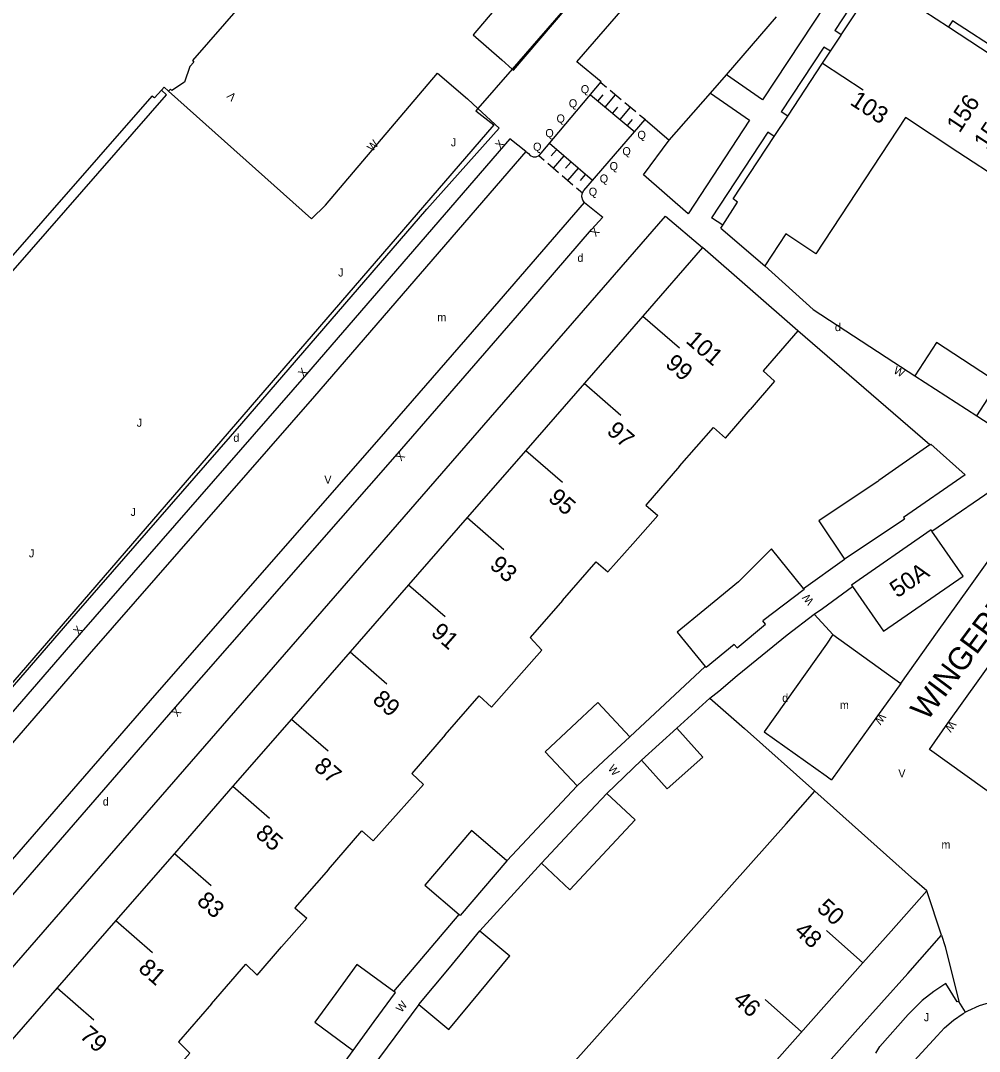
# Model space of a CAD drawing. Extents: x 134999 to 136502, y 457398 to 459002.
# Drawn here: x 135294.2 to 135353.4, y 457659.1 to 457722.8 of the extents above; entities that cross this region are included whole.
import ezdxf

# ---------------------------------------------------------------- set-up
doc = ezdxf.new("R2010")
doc.units = 0
for name, color, linetype in [('RI_DGTB_15', 7, 'Continuous'), ('RI_DGTB_2', 7, 'Continuous'), ('RI_DGTB_29', 7, 'Continuous'), ('RI_DGTB_30', 7, 'Continuous'), ('RI_DGTB_31', 7, 'Continuous'), ('RI_DGTB_35', 7, 'Continuous'), ('RI_DGTB_36', 7, 'Continuous'), ('RI_DGTB_37', 7, 'Continuous'), ('RI_DGTB_4', 7, 'Continuous'), ('RI_DGTB_43', 7, 'Continuous'), ('RI_DGTB_48', 7, 'Continuous'), ('RI_DGTB_5', 7, 'Continuous'), ('RI_DGTB_53', 7, 'Continuous'), ('RI_DGTB_54', 7, 'Continuous'), ('RI_DGTB_55', 7, 'Continuous'), ('RI_DGTB_6', 7, 'Continuous')]:
    doc.layers.add(name, color=color, linetype=linetype)

msp = doc.modelspace()

# ---------------------------------------------------------------- linework, layer by layer
at = {"layer": 'RI_DGTB_15'}
for p, q in [((135343.741, 457720.145), (135346.249, 457718.499)), ((135332.636, 457704.527), (135334.897, 457702.556)), ((135329.018, 457700.378), (135331.279, 457698.407)), ((135325.4, 457696.229), (135327.661, 457694.258)), ((135321.782, 457692.08), (135324.043, 457690.109)), ((135318.164, 457687.931), (135320.425, 457685.96)), ((135314.546, 457683.782), (135316.807, 457681.811)), ((135310.928, 457679.633), (135313.189, 457677.662)), ((135307.31, 457675.484), (135309.571, 457673.513)), ((135303.692, 457671.335), (135305.953, 457669.364)), ((135300.074, 457667.186), (135302.335, 457665.215)), ((135346.225, 457664.577), (135343.982, 457666.569)), ((135296.456, 457663.037), (135298.717, 457661.066)), ((135342.441, 457660.314), (135340.198, 457662.306))]:
    msp.add_line(p, q, dxfattribs=at)
at = {"layer": 'RI_DGTB_2'}
msp.add_line((135337.459, 457709.965), (135340.181, 457707.64), dxfattribs=at)
for points in [[(135344.893, 457721.893), (135347.062, 457725.193), (135347.117, 457725.277), (135347.953, 457724.727)], [(135349.991, 457723.39), (135351.511, 457722.392)], [(135351.511, 457722.392), (135355.473, 457719.793)], [(135344.228, 457720.884), (135344.884, 457721.88), (135344.893, 457721.893)], [(135343.741, 457720.145), (135344.228, 457720.884)], [(135341.587, 457716.875), (135343.741, 457720.145)], [(135348.857, 457716.787), (135343.319, 457708.382), (135341.463, 457709.603), (135340.181, 457707.64)], [(135340.757, 457715.615), (135341.587, 457716.875)], [(135352.102, 457714.66), (135348.857, 457716.787)], [(135337.578, 457710.148), (135338.492, 457711.56), (135338.218, 457711.761), (135340.757, 457715.615)], [(135360.141, 457709.392), (135354.871, 457712.845), (135352.102, 457714.66)], [(135337.459, 457709.965), (135337.578, 457710.148)], [(135350.446, 457691.317), (135345.519, 457687.906), (135345.584, 457687.813)], [(135345.584, 457687.813), (135347.494, 457685.054), (135352.42, 457688.466), (135350.492, 457691.25)], [(135350.492, 457691.25), (135350.446, 457691.317)], [(135341.479, 457673.165), (135343.265, 457675.172)], [(135343.265, 457675.172), (135349.426, 457669.682)], [(135339.304, 457670.719), (135341.479, 457673.165)], [(135335.451, 457666.387), (135339.304, 457670.719)], [(135350.175, 457669.019), (135349.426, 457669.682)], [(135347.976, 457666.538), (135350.175, 457669.019)], [(135331.702, 457662.171), (135335.451, 457666.387)], [(135346.23, 457664.572), (135347.976, 457666.538)], [(135342.377, 457660.238), (135346.23, 457664.572)], [(135327.941, 457657.942), (135331.702, 457662.171)], [(135338.631, 457656.019), (135342.377, 457660.238)]]:
    msp.add_lwpolyline(points, dxfattribs=at)
at = {"layer": 'RI_DGTB_31'}
for p, q in [((135330.037, 457718.963), (135330.382, 457718.675)), ((135329.394, 457718.196), (135332.135, 457715.915)), ((135329.857, 457717.811), (135330.177, 457718.196)), ((135330.314, 457717.431), (135330.953, 457718.2)), ((135330.611, 457718.485), (135331.296, 457717.915)), ((135330.77, 457717.051), (135331.09, 457717.436)), ((135331.227, 457716.671), (135331.867, 457717.44)), ((135331.524, 457717.725), (135332.209, 457717.155)), ((135331.684, 457716.291), (135332.003, 457716.676)), ((135332.437, 457716.965), (135332.79, 457716.672)), ((135329.524, 457712.897), (135326.862, 457715.178)), ((135327.304, 457714.799), (135326.979, 457714.42)), ((135326.543, 457714.135), (135326.202, 457714.427)), ((135327.747, 457714.419), (135327.097, 457713.66)), ((135327.429, 457713.375), (135326.764, 457713.945)), ((135328.191, 457714.039), (135327.865, 457713.66)), ((135328.634, 457713.659), (135327.983, 457712.9)), ((135328.316, 457712.615), (135327.651, 457713.185)), ((135329.077, 457713.279), (135328.752, 457712.9)), ((135328.9, 457712.115), (135328.538, 457712.425))]:
    msp.add_line(p, q, dxfattribs=at)
at = {"layer": 'RI_DGTB_4'}
for p, q in [((135336.325, 457708.754), (135332.638, 457704.526)), ((135342.218, 457703.62), (135336.325, 457708.754)), ((135332.638, 457704.526), (135329.019, 457700.377)), ((135329.019, 457700.377), (135325.401, 457696.228)), ((135325.401, 457696.228), (135321.783, 457692.079)), ((135321.783, 457692.079), (135318.165, 457687.93)), ((135318.165, 457687.93), (135314.547, 457683.781)), ((135314.547, 457683.781), (135310.928, 457679.633)), ((135310.928, 457679.633), (135307.31, 457675.484)), ((135307.31, 457675.484), (135303.692, 457671.335)), ((135303.692, 457671.335), (135300.074, 457667.186)), ((135300.074, 457667.186), (135296.456, 457663.037)), ((135296.456, 457663.037), (135292.949, 457659.016))]:
    msp.add_line(p, q, dxfattribs=at)
for points in [[(135310.705, 457728.382), (135311.252, 457727.392), (135310.849, 457726.487), (135310.114, 457725.983), (135309.89, 457726.153), (135304.806, 457720.309), (135304.895, 457720.207), (135304.654, 457719.941), (135304.317, 457718.97), (135303.528, 457718.455), (135303.458, 457718.538), (135303.325, 457718.417)], [(135302.891, 457718.474), (135302.467, 457718.005), (135302.295, 457718.113), (135278.78, 457691.233), (135278.907, 457691.093), (135277.688, 457689.697), (135275.624, 457691.499), (135274.242, 457689.916), (135267.906, 457695.492), (135269.162, 457696.919), (135269.235, 457696.851), (135272.195, 457700.215), (135272.12, 457700.282), (135272.992, 457701.274), (135272.039, 457702.112), (135273.325, 457703.592), (135273.401, 457703.527), (135291.543, 457724.381), (135291.468, 457724.447), (135292.61, 457725.76)], [(135303.325, 457718.417), (135303.058, 457718.659), (135302.891, 457718.474)]]:
    msp.add_lwpolyline(points, dxfattribs=at)
at = {"layer": 'RI_DGTB_48'}
for p, q in [((135331.403, 457727.651), (135324.569, 457719.788)), ((135350.492, 457691.25), (135356.071, 457695.073)), ((135338.907, 457679.043), (135343.265, 457675.172))]:
    msp.add_line(p, q, dxfattribs=at)
for points in [[(135322.448, 457717.348), (135322.32, 457717.201), (135323.431, 457716.332), (135290.7, 457678.464), (135285.527, 457682.935)], [(135343.222, 457686.107), (135343.74, 457686.465), (135345.584, 457687.813)], [(135336.777, 457680.921), (135338.907, 457679.043)]]:
    msp.add_lwpolyline(points, dxfattribs=at)
at = {"layer": 'RI_DGTB_5'}
for points in [[(135342.218, 457703.62), (135340.064, 457701.155), (135340.761, 457700.501), (135339.258, 457698.755)], [(135334.904, 457695.247), (135337.001, 457697.647), (135337.731, 457696.981), (135339.258, 457698.755)], [(135334.904, 457695.247), (135332.812, 457692.852), (135333.561, 457692.211), (135332.008, 457690.468)], [(135327.66, 457686.956), (135329.756, 457689.354), (135330.461, 457688.731), (135332.008, 457690.468)], [(135327.66, 457686.956), (135325.673, 457684.681), (135326.401, 457683.881), (135324.836, 457682.115)], [(135320.427, 457678.656), (135322.521, 457681.064), (135323.281, 457680.361), (135324.836, 457682.115)], [(135320.427, 457678.656), (135318.352, 457676.27), (135319.091, 457675.591), (135317.547, 457673.863)], [(135313.202, 457670.348), (135315.276, 457672.732), (135315.981, 457672.111), (135317.547, 457673.863)], [(135313.202, 457670.348), (135311.135, 457667.971), (135311.871, 457667.341), (135310.317, 457665.56)], [(135305.977, 457662.04), (135308.109, 457664.491), (135308.801, 457663.821), (135310.317, 457665.56)], [(135305.977, 457662.04), (135303.946, 457659.706), (135304.651, 457658.991), (135303.1, 457657.245)]]:
    msp.add_lwpolyline(points, dxfattribs=at)
at = {"layer": 'RI_DGTB_53'}
for p, q in [((135346.986, 457725.951), (135344.489, 457722.159)), ((135351.76, 457722.771), (135351.511, 457722.392)), ((135358.542, 457718.33), (135351.76, 457722.771)), ((135344.893, 457721.893), (135344.489, 457722.159)), ((135343.824, 457721.148), (135341.184, 457717.14)), ((135324.569, 457719.788), (135322.448, 457717.348)), ((135336.811, 457718.295), (135337.795, 457719.434)), ((135334.27, 457715.4), (135336.811, 457718.295)), ((135323.758, 457716.133), (135322.448, 457717.348)), ((135341.587, 457716.875), (135341.184, 457717.14)), ((135325.395, 457714.7), (135324.42, 457715.48)), ((135332.666, 457713.252), (135334.27, 457715.4)), ((135340.355, 457715.878), (135336.883, 457710.606)), ((135337.578, 457710.148), (135336.883, 457710.606)), ((135348.149, 457701.68), (135349.447, 457700.844)), ((135334.729, 457679.068), (135336.777, 457680.921)), ((135332.543, 457677.099), (135330.405, 457675.045)), ((135343.952, 457676.134), (135344.297, 457675.888)), ((135322.567, 457666.549), (135326.376, 457670.729))]:
    msp.add_line(p, q, dxfattribs=at)
for points in [[(135324.569, 457719.788), (135324.646, 457719.721), (135331.403, 457727.651)], [(135330.06, 457718.99), (135328.562, 457720.222), (135335.083, 457727.765), (135335.203, 457727.903)], [(135345.487, 457726.152), (135340.034, 457717.881), (135337.795, 457719.434)], [(135337.795, 457719.434), (135340.885, 457723.015)], [(135344.228, 457720.884), (135343.824, 457721.148)], [(135325.674, 457714.454), (135325.85, 457714.372), (135326.044, 457714.368), (135326.224, 457714.441), (135326.36, 457714.58), (135330.06, 457718.99)], [(135336.811, 457718.295), (135339.232, 457716.623), (135335.439, 457710.847), (135332.666, 457713.252)], [(135329.021, 457711.551), (135329.01, 457711.56), (135328.928, 457711.681), (135328.871, 457711.883), (135328.892, 457712.093), (135328.99, 457712.28), (135332.78, 457716.66)], [(135332.78, 457716.66), (135334.27, 457715.4)], [(135340.757, 457715.615), (135340.355, 457715.878)], [(135325.395, 457714.7), (135325.57, 457714.56), (135325.674, 457714.454)], [(135329.021, 457711.551), (135330.16, 457710.63), (135329.47, 457709.87)], [(135340.181, 457707.64), (135343.148, 457704.94), (135348.149, 457701.68)], [(135353.264, 457698.367), (135357.51, 457695.616), (135357.91, 457695.35)], [(135352.769, 457687.722), (135353.814, 457689.168), (135357.47, 457694.273)], [(135348.565, 457681.833), (135350.843, 457685.031), (135352.769, 457687.722)], [(135336.777, 457680.921), (135337.33, 457681.359), (135338.454, 457682.318), (135341.548, 457684.839), (135343.222, 457686.107)], [(135343.222, 457686.107), (135344.17, 457685.079), (135344.373, 457684.858)], [(135344.373, 457684.858), (135343.984, 457684.257), (135340.126, 457678.856), (135343.952, 457676.134)], [(135344.373, 457684.858), (135348.565, 457681.833)], [(135354.85, 457674.512), (135350.337, 457677.758), (135351.478, 457679.373), (135355.431, 457684.893)], [(135348.565, 457681.833), (135347.14, 457679.836), (135344.297, 457675.888)], [(135351.089, 457666.291), (135350.175, 457669.019)], [(135335.258, 457648.482), (135345.762, 457660.299), (135348.997, 457663.927), (135351.089, 457666.291)], [(135351.089, 457666.291), (135351.31, 457665.578), (135352.156, 457662.193)], [(135351.357, 457663.303), (135350.606, 457662.803), (135349.902, 457662.24), (135349.251, 457661.616), (135349.03, 457661.377)], [(135352.156, 457662.193), (135352.063, 457662.169), (135351.357, 457663.303)], [(135318.799, 457661.996), (135315.358, 457657.38)], [(135352.577, 457661.527), (135352.156, 457662.193)], [(135356.516, 457662.391), (135355.728, 457662.39), (135354.945, 457662.309), (135354.174, 457662.149), (135353.424, 457661.911), (135352.701, 457661.599), (135352.577, 457661.527)], [(135347.025, 457658.99), (135347.268, 457659.411), (135349.03, 457661.377)], [(135350.813, 457660.074), (135351.281, 457660.571), (135351.828, 457661.036), (135352.424, 457661.438), (135352.577, 457661.527)], [(135349.055, 457658.112), (135349.407, 457658.518), (135350.813, 457660.074)]]:
    msp.add_lwpolyline(points, dxfattribs=at)
at = {"layer": 'RI_DGTB_54'}
for p, q in [((135350.359, 457696.568), (135342.218, 457703.62)), ((135342.563, 457687.691), (135345.092, 457689.515)), ((135331.828, 457678.541), (135336.494, 457682.89)), ((135324.227, 457670.879), (135328.568, 457675.513)), ((135317.248, 457662.814), (135321.279, 457667.559)), ((135311.176, 457654.283), (135314.74, 457659.169))]:
    msp.add_line(p, q, dxfattribs=at)
for points in [[(135225.859, 457592.087), (135229.093, 457596.234), (135237.631, 457607.935), (135241.478, 457613.178), (135245.725, 457618.923), (135249.918, 457624.708), (135250.744, 457625.814), (135259.283, 457637.533), (135261.865, 457641.002), (135264.418, 457644.492), (135267.969, 457649.188), (135273.531, 457656.651), (135279.029, 457664.161), (135281.898, 457668.107), (135282.256, 457668.535), (135282.636, 457668.944), (135289.862, 457677.192), (135297.616, 457686.163), (135307.857, 457697.893), (135319.282, 457711.138), (135323.758, 457716.133)], [(135324.42, 457715.48), (135311.855, 457700.931), (135297.939, 457684.983), (135283.559, 457668.38), (135282.566, 457667.276), (135279.957, 457663.705)], [(135325.395, 457714.7), (135312.345, 457699.589), (135298.429, 457683.641), (135284.049, 457667.038), (135283.056, 457665.934), (135276.706, 457657.242), (135270.861, 457649.099), (135263.416, 457638.885), (135260.839, 457635.407), (135251.887, 457623.111), (135247.499, 457617.047), (135241.313, 457608.66)], [(135231.817, 457587.839), (135240.607, 457599.736), (135247.755, 457609.38), (135250.141, 457612.706), (135257.778, 457623.177), (135262.982, 457630.275), (135267.289, 457636.273), (135273.154, 457644.368), (135275.511, 457647.533), (135286.065, 457661.986), (135287.341, 457663.633), (135288.68, 457665.23), (135289.334, 457665.967), (135302.48, 457681.093), (135316.344, 457696.917), (135323.753, 457705.451), (135329.021, 457711.551)], [(135256.725, 457614.333), (135290.608, 457660.715), (135292.406, 457662.843), (135334.042, 457710.706), (135336.325, 457708.754)], [(135285.792, 457659.172), (135287.196, 457661.094), (135288.472, 457662.741), (135289.811, 457664.338), (135290.465, 457665.075), (135303.611, 457680.201), (135317.475, 457696.025), (135324.884, 457704.559), (135329.47, 457709.87)]]:
    msp.add_lwpolyline(points, dxfattribs=at)
at = {"layer": 'RI_DGTB_55'}
for points in [[(135319.212, 457743.021), (135317.2, 457740.72), (135329.24, 457730.25), (135322.16, 457721.91), (135323.914, 457720.356), (135324.569, 457719.788)], [(135303.325, 457718.417), (135312.17, 457710.54), (135313.02, 457711.37), (135319.95, 457719.53), (135321.8, 457717.95), (135322.448, 457717.348)], [(135279.141, 457690.661), (135303.201, 457718.191), (135302.891, 457718.474)]]:
    msp.add_lwpolyline(points, dxfattribs=at)
at = {"layer": 'RI_DGTB_6'}
for points in [[(135353.264, 457698.367), (135354.592, 457700.413), (135350.776, 457702.89), (135349.447, 457700.844)], [(135349.447, 457700.844), (135353.264, 457698.367)], [(135350.359, 457696.568), (135347.216, 457694.367), (135347.157, 457694.312), (135345.571, 457693.256)], [(135350.359, 457696.568), (135350.421, 457696.611), (135352.551, 457694.711), (135348.734, 457692.089), (135348.808, 457691.976), (135347.103, 457690.847)], [(135345.571, 457693.256), (135343.514, 457691.886), (135345.092, 457689.515)], [(135347.103, 457690.847), (135345.092, 457689.515)], [(135342.563, 457687.691), (135340.576, 457690.144), (135338.554, 457688.114), (135336.469, 457686.408)], [(135342.563, 457687.691), (135342.611, 457687.631), (135340.051, 457685.693)], [(135336.469, 457686.408), (135334.756, 457685.005), (135336.494, 457682.89)], [(135338.285, 457684.25), (135338.459, 457684.044), (135340.212, 457685.499), (135340.051, 457685.693)], [(135338.285, 457684.25), (135336.546, 457682.827), (135336.494, 457682.89)], [(135331.828, 457678.541), (135329.853, 457680.651), (135328.228, 457679.131)], [(135328.228, 457679.131), (135326.604, 457677.611), (135328.568, 457675.513)], [(135332.543, 457677.099), (135334.729, 457679.068)], [(135334.729, 457679.068), (135336.333, 457677.287), (135334.147, 457675.318), (135332.543, 457677.099)], [(135330.198, 457677.027), (135331.828, 457678.541)], [(135328.568, 457675.513), (135330.198, 457677.027)], [(135330.405, 457675.045), (135328.39, 457672.887)], [(135330.143, 457671.251), (135332.158, 457673.409), (135330.405, 457675.045)], [(135324.227, 457670.879), (135322.055, 457672.743), (135320.61, 457671.058)], [(135328.39, 457672.887), (135326.376, 457670.729)], [(135320.61, 457671.058), (135319.165, 457669.373), (135321.279, 457667.559)], [(135324.227, 457670.879), (135322.783, 457669.195)], [(135326.376, 457670.729), (135328.128, 457669.093), (135330.143, 457671.251)], [(135322.783, 457669.195), (135321.337, 457667.509), (135321.279, 457667.559)], [(135320.683, 457664.272), (135322.567, 457666.549)], [(135322.567, 457666.549), (135324.416, 457665.019)], [(135317.248, 457662.814), (135314.972, 457664.473), (135313.667, 457662.688)], [(135322.532, 457662.742), (135324.416, 457665.019)], [(135318.799, 457661.996), (135320.683, 457664.272)], [(135313.667, 457662.688), (135312.362, 457660.903), (135314.74, 457659.169)], [(135316.043, 457660.951), (135317.35, 457662.739), (135317.248, 457662.814)], [(135320.648, 457660.466), (135322.532, 457662.742)], [(135318.799, 457661.996), (135320.648, 457660.466)], [(135314.74, 457659.169), (135316.043, 457660.951)]]:
    msp.add_lwpolyline(points, dxfattribs=at)

# ---------------------------------------------------------------- texts
at = {"layer": 'RI_DGTB_29'}
for p in [(135328.592, 457707.881), (135344.502, 457703.599), (135307.332, 457696.761), (135341.244, 457680.692), (135299.262, 457674.291)]:
    msp.add_text('d', height=0.5, dxfattribs=at).set_placement(p)
at = {"layer": 'RI_DGTB_30'}
for s, height, rotation, p in [('V', 0.5, 137.60134, (135307.554, 457718.126)), ('W', 0.5, 48.04904, (135315.917, 457714.656)), ('X', 0.5, 48.75082, (135323.83, 457714.806)), ('X', 0.5, 228.35943, (135329.636, 457710.057)), ('X', 0.5, 49.05181, (135311.665, 457700.712)), ('W', 0.5, 331.00536, (135348.076, 457701.032)), ('X', 0.499, 228.98866, (135317.61, 457696.187)), ('W', 0.5, 129.23692, (135343.231, 457686.931)), ('X', 0.5, 49.05181, (135297.772, 457684.79)), ('X', 0.499, 228.98866, (135303.776, 457680.39)), ('W', 0.5, 234.49889, (135347.285, 457680.04)), ('W', 0.5, 234.75992, (135351.622, 457679.577)), ('W', 0.5, 308.56981, (135330.449, 457676.566)), ('W', 0.5, 50.86509, (135317.72, 457661.473))]:
    msp.add_text(s, height=height, rotation=rotation, dxfattribs=at).set_placement(p)
for p in [(135312.954, 457694.173), (135348.417, 457676.032)]:
    msp.add_text('V', height=0.5, dxfattribs=at).set_placement(p)
at = {"layer": 'RI_DGTB_31'}
for s, rotation, p in [('Q', 359.99965, (135328.8, 457718.29)), ('Q', 359.99965, (135328.06, 457717.42)), ('Q', 359.99965, (135327.3, 457716.48)), ('Q', 359.99965, (135326.61, 457715.58)), ('J', 359.99973, (135320.771, 457715.012)), ('Q', 359.99965, (135332.3, 457715.47)), ('Q', 359.99965, (135325.85, 457714.74)), ('Q', 359.99965, (135331.37, 457714.46)), ('Q', 359.99965, (135330.58, 457713.54)), ('Q', 359.99965, (135329.97, 457712.77)), ('Q', 359.99965, (135329.29, 457711.96)), ('J', 359.99973, (135313.811, 457706.972)), ('J', 359.99973, (135301.361, 457697.692)), ('J', 359.99973, (135300.981, 457692.182)), ('J', 359.99973, (135294.701, 457689.622))]:
    msp.add_text(s, height=0.5, rotation=rotation, dxfattribs=at).set_placement(p)
msp.add_text('J', height=0.5, dxfattribs=at).set_placement((135349.998, 457660.968))
at = {"layer": 'RI_DGTB_35'}
for s, rotation, p in [('103', 326.7107, (135345.375, 457717.631)), ('156', 56.71, (135352.204, 457715.795)), ('101', 318.9082, (135335.229, 457702.933)), ('50A', 34.4595, (135348.353, 457687.085)), ('50', 318.4122, (135343.319, 457667.857))]:
    msp.add_text(s, height=1.054, rotation=rotation, dxfattribs=at).set_placement(p)
at = {"layer": 'RI_DGTB_36'}
for s, rotation, p in [('154', 56.71, (135353.886, 457714.747)), ('99', 318.9082, (135333.958, 457701.482)), ('97', 318.9082, (135330.341, 457697.331)), ('95', 318.9082, (135326.722, 457693.184)), ('93', 318.9082, (135323.105, 457689.033)), ('91', 318.9082, (135319.487, 457684.885)), ('89', 318.9082, (135315.868, 457680.736)), ('87', 318.9082, (135312.25, 457676.588)), ('85', 318.9082, (135308.633, 457672.437)), ('83', 318.9082, (135305.014, 457668.29)), ('48', 318.4122, (135341.933, 457666.444)), ('81', 318.9082, (135301.397, 457664.14)), ('46', 318.4122, (135338.143, 457662.187)), ('79', 318.9082, (135297.779, 457659.991))]:
    msp.add_text(s, height=1.054, rotation=rotation, dxfattribs=at).set_placement(p)
at = {"layer": 'RI_DGTB_37'}
msp.add_text('WINGERDPLAATS', height=1.4, rotation=53.27028, dxfattribs=at).set_placement((135350.194, 457679.464))
at = {"layer": 'RI_DGTB_43'}
for p in [(135319.933, 457704.205), (135344.804, 457680.26), (135351.083, 457671.63)]:
    msp.add_text('m', height=0.5, dxfattribs=at).set_placement(p)

doc.saveas('drawing.dxf')
